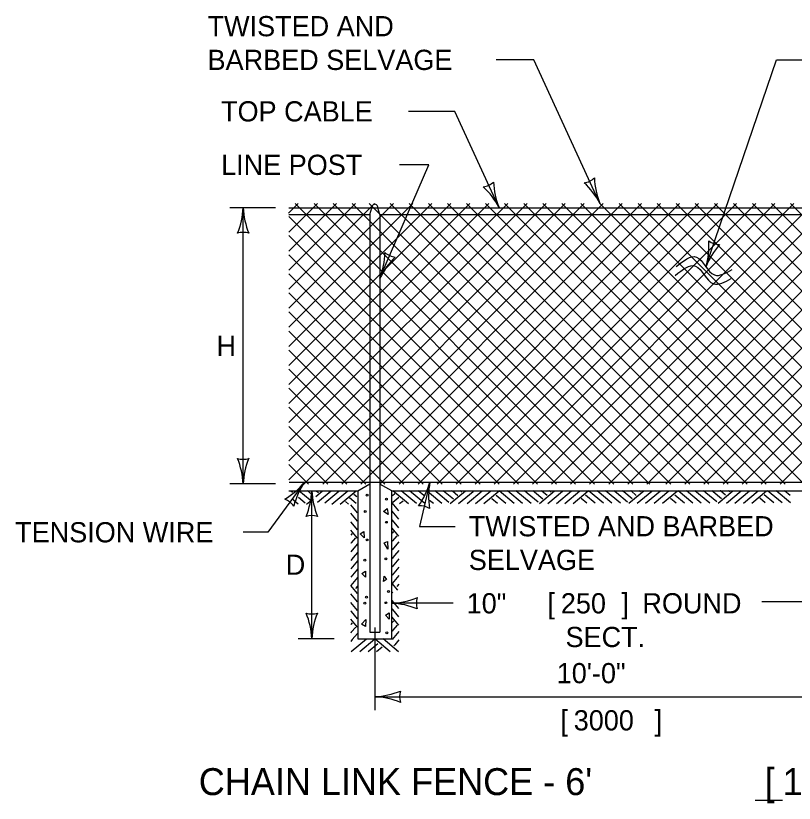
# Model space of a CAD drawing. Extents: x 49973.1 to 50021, y 49987.6 to 50015.4.
# Drawn here: x 49973.659 to 49975.97, y 50013.026 to 50015.363 of the extents above; entities that cross this region are included whole.
import ezdxf

# ---------------------------------------------------------------- set-up
doc = ezdxf.new("R2010")
doc.units = 0
for name, color, linetype in [('Level 1', 7, 'Continuous'), ('Level 2', 7, 'Continuous'), ('Level 3', 7, 'Continuous'), ('Level 6', 7, 'Continuous')]:
    doc.layers.add(name, color=color, linetype=linetype)

msp = doc.modelspace()

# ---------------------------------------------------------------- linework, layer by layer
at = {"layer": 'Level 1'}
for p, q in [((49974.4694, 50014.7766), (49974.4981, 50014.8053)), ((49974.4702, 50014.7208), (49974.5547, 50014.8053)), ((49974.4702, 50014.6642), (49974.6113, 50014.8053)), ((49974.4702, 50014.6076), (49974.6679, 50014.8053)), ((49974.4702, 50014.7932), (49977.3392, 50014.7932)), ((49974.4703, 50014.5513), (49974.7243, 50014.8053)), ((49974.4703, 50014.4947), (49974.7809, 50014.8053)), ((49974.4703, 50014.2683), (49975.0073, 50014.8053)), ((49974.4703, 50014.2119), (49975.0637, 50014.8053)), ((49974.4703, 50014.3815), (49974.8941, 50014.8053)), ((49974.4703, 50014.3249), (49974.9507, 50014.8053)), ((49974.4703, 50014.4381), (49974.8375, 50014.8053)), ((49974.4704, 50014.1554), (49975.1203, 50014.8053)), ((49974.4704, 50014.0422), (49975.2335, 50014.8053)), ((49974.4704, 50014.0988), (49975.1769, 50014.8053)), ((49974.4704, 50013.9856), (49975.2901, 50014.8053)), ((49974.4884, 50014.8053), (49975.321, 50013.9729)), ((49974.5143, 50013.9729), (49975.3467, 50014.8053)), ((49974.5452, 50014.8053), (49975.3776, 50013.9729)), ((49974.5709, 50013.9729), (49975.4033, 50014.8053)), ((49974.6016, 50014.8053), (49975.4342, 50013.9729)), ((49974.6273, 50013.9729), (49975.4597, 50014.8053)), ((49974.6582, 50014.8053), (49975.4908, 50013.9729)), ((49974.6839, 50013.9729), (49975.5163, 50014.8053)), ((49974.7087, 50014.8053), (49975.5416, 50013.9729)), ((49974.7102, 50014.7732), (49974.7165, 50014.7927)), ((49974.7402, 50014.7732), (49974.7342, 50014.793)), ((49974.7405, 50013.9729), (49975.5729, 50014.8053)), ((49974.7707, 50014.8053), (49975.6038, 50013.9729)), ((49974.7971, 50013.9729), (49975.6295, 50014.8053)), ((49974.8275, 50014.8053), (49975.6604, 50013.9729)), ((49974.8537, 50013.9729), (49975.6861, 50014.8053)), ((49974.8843, 50014.8053), (49975.717, 50013.9729)), ((49974.9103, 50013.9729), (49975.7427, 50014.8053)), ((49974.9407, 50014.8053), (49975.7736, 50013.9729)), ((49974.9667, 50013.9729), (49975.7991, 50014.8053)), ((49974.9976, 50014.8053), (49975.8302, 50013.9729)), ((49975.0233, 50013.9729), (49975.8557, 50014.8053)), ((49975.0537, 50014.8053), (49975.8866, 50013.9729)), ((49975.0799, 50013.9729), (49975.9123, 50014.8053)), ((49975.1101, 50014.8053), (49975.9432, 50013.9729)), ((49975.1365, 50013.9729), (49975.9689, 50014.8053)), ((49975.1672, 50014.8053), (49975.9998, 50013.9729)), ((49975.1931, 50013.9729), (49976.0255, 50014.8053)), ((49975.2235, 50014.8053), (49976.0564, 50013.9729)), ((49975.2497, 50013.9729), (49976.0821, 50014.8053)), ((49975.2804, 50014.8053), (49976.113, 50013.9729)), ((49975.3061, 50013.9729), (49976.1385, 50014.8053)), ((49975.337, 50014.8053), (49976.1696, 50013.9729)), ((49975.3627, 50013.9729), (49976.1951, 50014.8053)), ((49975.3935, 50014.8053), (49976.2262, 50013.9729)), ((49975.4193, 50013.9729), (49976.2517, 50014.8053)), ((49975.45, 50014.8053), (49976.2826, 50013.9729)), ((49975.4759, 50013.9729), (49976.3083, 50014.8053)), ((49975.5068, 50014.8053), (49976.3392, 50013.9729)), ((49975.5325, 50013.9729), (49976.3649, 50014.8053)), ((49975.5633, 50014.8053), (49976.3958, 50013.9729)), ((49975.5891, 50013.9729), (49976.4215, 50014.8053)), ((49975.6199, 50014.8053), (49976.4524, 50013.9729)), ((49975.6457, 50013.9729), (49976.4781, 50014.8053)), ((49975.6765, 50014.8053), (49976.509, 50013.9729)), ((49975.7021, 50013.9729), (49976.5345, 50014.8053)), ((49975.7331, 50014.8053), (49976.5656, 50013.9729)), ((49975.7587, 50013.9729), (49976.5911, 50014.8053)), ((49975.7895, 50014.8053), (49976.622, 50013.9729)), ((49975.8153, 50013.9729), (49976.6477, 50014.8053)), ((49975.8461, 50014.8053), (49976.6786, 50013.9729)), ((49975.8719, 50013.9729), (49976.7043, 50014.8053)), ((49975.9027, 50014.8053), (49976.7352, 50013.9729)), ((49975.9285, 50013.9729), (49976.7609, 50014.8053)), ((49975.9593, 50014.8053), (49976.7918, 50013.9729)), ((49974.4702, 50014.7732), (49974.7102, 50014.7732)), ((49974.7102, 50014.7732), (49974.7102, 50013.5332)), ((49974.7402, 50014.7732), (49974.7402, 50013.9729)), ((49974.7402, 50014.7732), (49976.1102, 50014.7732)), ((49974.4702, 50014.7668), (49975.2644, 50013.9729)), ((49974.4702, 50014.7102), (49975.2078, 50013.9729)), ((49974.4702, 50014.6534), (49975.1512, 50013.9729)), ((49974.4702, 50014.5966), (49975.0946, 50013.9729)), ((49974.4703, 50014.5401), (49975.038, 50013.9729)), ((49974.4703, 50014.4838), (49974.9814, 50013.9729)), ((49974.4703, 50014.4266), (49974.9248, 50013.9729)), ((49974.4703, 50014.3703), (49974.8682, 50013.9729)), ((49974.4703, 50014.3138), (49974.8116, 50013.9729)), ((49974.4703, 50014.2575), (49974.755, 50013.9729)), ((49974.4703, 50014.2008), (49974.6984, 50013.9729)), ((49974.4704, 50014.1442), (49974.6418, 50013.9729)), ((49974.4704, 50014.0876), (49974.5852, 50013.9729)), ((49974.4704, 50014.031), (49974.5286, 50013.9729)), ((49974.4705, 50013.9786), (49977.4631, 50013.9786)), ((49974.4704, 50013.9532), (49974.6752, 50013.9532)), ((49974.4811, 50013.9478), (49974.476, 50013.952)), ((49974.4998, 50013.9531), (49974.4997, 50013.9532)), ((49974.5335, 50013.925), (49974.5, 50013.9532)), ((49974.5291, 50013.9495), (49974.5252, 50013.9528)), ((49974.5503, 50013.9365), (49974.5687, 50013.9519)), ((49974.5525, 50013.9508), (49974.5504, 50013.9525)), ((49974.5575, 50013.9466), (49974.5525, 50013.9508)), ((49974.5552, 50013.9196), (49974.5953, 50013.9532)), ((49974.5769, 50013.917), (49974.6187, 50013.9519)), ((49974.5905, 50013.9492), (49974.5931, 50013.9514)), ((49974.5975, 50013.9131), (49974.6453, 50013.9532)), ((49974.6225, 50013.9131), (49974.6695, 50013.9526)), ((49974.6752, 50013.9532), (49974.7102, 50013.9732)), ((49974.6752, 50013.9532), (49974.6752, 50013.5141)), ((49974.7402, 50013.9729), (49974.7402, 50013.5332)), ((49974.7752, 50013.9531), (49974.7402, 50013.9725)), ((49974.7752, 50013.9532), (49976.0752, 50013.9532)), ((49974.7752, 50013.5141), (49974.7752, 50013.9531)), ((49974.8251, 50013.914), (49974.7791, 50013.9526)), ((49974.8489, 50013.915), (49974.8034, 50013.9532)), ((49974.8739, 50013.915), (49974.8285, 50013.9531)), ((49974.8702, 50013.9391), (49974.8534, 50013.9531)), ((49974.9125, 50013.9455), (49974.9033, 50013.9531)), ((49974.9341, 50013.9484), (49974.9284, 50013.9531)), ((49974.9489, 50013.915), (49974.9942, 50013.9531)), ((49974.9555, 50013.9514), (49974.9534, 50013.9531)), ((49974.9712, 50013.9383), (49974.9555, 50013.9514)), ((49974.9739, 50013.915), (49975.0169, 50013.9511)), ((49974.9789, 50013.9527), (49974.9784, 50013.9531)), ((49974.9839, 50013.9485), (49974.9789, 50013.9527)), ((49974.9989, 50013.915), (49975.0442, 50013.9531)), ((49975.0169, 50013.9511), (49975.0192, 50013.9531)), ((49975.0239, 50013.915), (49975.0692, 50013.9531)), ((49975.0489, 50013.915), (49975.0942, 50013.9531)), ((49975.139, 50013.9155), (49975.0942, 50013.9531)), ((49975.164, 50013.9155), (49975.119, 50013.9531)), ((49975.189, 50013.9155), (49975.144, 50013.9531)), ((49975.1776, 50013.946), (49975.169, 50013.9531)), ((49975.1992, 50013.9489), (49975.1941, 50013.9531)), ((49975.214, 50013.9155), (49975.2587, 50013.9531)), ((49975.2206, 50013.9519), (49975.2191, 50013.9531)), ((49975.2363, 50013.9388), (49975.2206, 50013.9519)), ((49975.239, 50013.9155), (49975.282, 50013.9516)), ((49975.249, 50013.949), (49975.244, 50013.9532)), ((49975.264, 50013.9155), (49975.3087, 50013.9531)), ((49975.282, 50013.9516), (49975.2837, 50013.9531)), ((49975.289, 50013.9155), (49975.3337, 50013.9531)), ((49975.314, 50013.9155), (49975.3587, 50013.9531)), ((49975.4041, 50013.916), (49975.3598, 50013.9531)), ((49975.4291, 50013.916), (49975.3847, 50013.9531)), ((49975.4541, 50013.916), (49975.4097, 50013.9531)), ((49975.4427, 50013.9465), (49975.4347, 50013.9531)), ((49975.4643, 50013.9494), (49975.4598, 50013.9531)), ((49975.4791, 50013.916), (49975.5232, 50013.9531)), ((49975.4857, 50013.9524), (49975.4848, 50013.9531)), ((49975.5014, 50013.9393), (49975.4857, 50013.9524)), ((49975.5041, 50013.916), (49975.5471, 50013.9521)), ((49975.5141, 50013.9495), (49975.5098, 50013.9531)), ((49975.5291, 50013.916), (49975.5732, 50013.9531)), ((49975.5471, 50013.9521), (49975.5482, 50013.9531)), ((49975.5541, 50013.916), (49975.5982, 50013.9531)), ((49975.5791, 50013.916), (49975.6232, 50013.9531)), ((49975.6692, 50013.9165), (49975.6255, 50013.9531)), ((49975.6942, 50013.9165), (49975.6504, 50013.9531)), ((49975.7192, 50013.9165), (49975.6754, 50013.9531)), ((49975.7078, 50013.947), (49975.7004, 50013.9531)), ((49975.7294, 50013.9499), (49975.7255, 50013.9531)), ((49975.7442, 50013.9165), (49975.7877, 50013.9531)), ((49975.7508, 50013.9529), (49975.7505, 50013.9531)), ((49975.7665, 50013.9398), (49975.7508, 50013.9529)), ((49975.7692, 50013.9165), (49975.8122, 50013.9526)), ((49975.7792, 50013.95), (49975.7755, 50013.9531)), ((49975.7942, 50013.9165), (49975.8377, 50013.9531)), ((49975.8122, 50013.9526), (49975.8127, 50013.9531)), ((49975.8192, 50013.9165), (49975.8627, 50013.9531)), ((49975.8442, 50013.9165), (49975.8877, 50013.9531)), ((49975.9343, 50013.917), (49975.8912, 50013.9531)), ((49975.9593, 50013.917), (49975.9161, 50013.9531)), ((49975.9585, 50013.9386), (49975.9411, 50013.9531)), ((49974.4975, 50013.9131), (49974.4787, 50013.9288)), ((49974.4811, 50013.9478), (49974.4811, 50013.9478)), ((49974.5185, 50013.9166), (49974.4986, 50013.9333)), ((49974.5402, 50013.9403), (49974.5291, 50013.9495)), ((49974.5876, 50013.9468), (49974.5905, 50013.9492)), ((49974.6702, 50013.915), (49974.6504, 50013.9317)), ((49974.6713, 50013.9351), (49974.6633, 50013.9418)), ((49974.7778, 50013.9393), (49974.7844, 50013.9448)), ((49974.779, 50013.9193), (49974.7969, 50013.9343)), ((49974.9239, 50013.915), (49974.8874, 50013.9456)), ((49974.9448, 50013.9184), (49974.9125, 50013.9455)), ((49974.9587, 50013.9278), (49974.9341, 50013.9484)), ((49975.089, 50013.9155), (49975.0727, 50013.9292)), ((49975.114, 50013.9155), (49975.0856, 50013.9393)), ((49975.2099, 50013.9189), (49975.1776, 50013.946)), ((49975.2238, 50013.9283), (49975.1992, 50013.9489)), ((49975.3541, 50013.916), (49975.3378, 50013.9297)), ((49975.3791, 50013.916), (49975.3507, 50013.9398)), ((49975.475, 50013.9194), (49975.4427, 50013.9465)), ((49975.4889, 50013.9288), (49975.4643, 50013.9494)), ((49975.6192, 50013.9165), (49975.6029, 50013.9302)), ((49975.6442, 50013.9165), (49975.6158, 50013.9403)), ((49975.7401, 50013.9199), (49975.7078, 50013.947)), ((49975.754, 50013.9293), (49975.7294, 50013.9499)), ((49975.8843, 50013.917), (49975.868, 50013.9307)), ((49975.9093, 50013.917), (49975.8809, 50013.9408)), ((49974.5225, 50013.9131), (49974.5372, 50013.9254)), ((49974.6475, 50013.9131), (49974.6382, 50013.9209)), ((49974.6736, 50013.8875), (49974.6537, 50013.9112)), ((49974.7965, 50013.8934), (49974.7766, 50013.9171)), ((49974.7989, 50013.915), (49974.8091, 50013.9235)), ((49974.8989, 50013.915), (49974.8875, 50013.9246)), ((49974.6736, 50013.8625), (49974.6537, 50013.8862)), ((49974.7965, 50013.8684), (49974.7766, 50013.8921)), ((49974.6552, 50013.8595), (49974.6537, 50013.8612)), ((49974.6736, 50013.8375), (49974.6552, 50013.8595)), ((49974.7781, 50013.8654), (49974.7766, 50013.8671)), ((49974.7965, 50013.8434), (49974.7781, 50013.8654)), ((49974.6736, 50013.8125), (49974.6537, 50013.8362)), ((49974.7965, 50013.8184), (49974.7766, 50013.8421)), ((49974.6578, 50013.8265), (49974.6536, 50013.8215)), ((49974.668, 50013.8138), (49974.6549, 50013.7981)), ((49974.7807, 50013.8324), (49974.7765, 50013.8274)), ((49974.7909, 50013.8197), (49974.7778, 50013.804)), ((49974.6549, 50013.7981), (49974.6537, 50013.7966)), ((49974.6736, 50013.7954), (49974.6579, 50013.7767)), ((49974.7778, 50013.804), (49974.7766, 50013.8025)), ((49974.7965, 50013.8013), (49974.7808, 50013.7826)), ((49974.6579, 50013.7767), (49974.6537, 50013.7716)), ((49974.6736, 50013.7703), (49974.6608, 50013.7551)), ((49974.7808, 50013.7826), (49974.7766, 50013.7775)), ((49974.7965, 50013.7762), (49974.7837, 50013.761)), ((49974.6608, 50013.7551), (49974.6537, 50013.7465)), ((49974.6736, 50013.7453), (49974.6537, 50013.7215)), ((49974.7837, 50013.761), (49974.7766, 50013.7524)), ((49974.7965, 50013.7512), (49974.7766, 50013.7274)), ((49974.6736, 50013.7203), (49974.6537, 50013.6965)), ((49974.7965, 50013.7262), (49974.7766, 50013.7024)), ((49974.6736, 50013.6954), (49974.6537, 50013.6717)), ((49974.7965, 50013.7013), (49974.7766, 50013.6776)), ((49974.6736, 50013.648), (49974.6537, 50013.6717)), ((49974.6736, 50013.6703), (49974.6675, 50013.6631)), ((49974.7934, 50013.6576), (49974.7766, 50013.6776)), ((49974.7965, 50013.6762), (49974.7904, 50013.669)), ((49974.6736, 50013.623), (49974.6537, 50013.6467)), ((49974.779, 50013.6497), (49974.7766, 50013.6526)), ((49974.7965, 50013.6039), (49974.7766, 50013.6276)), ((49974.6736, 50013.598), (49974.6537, 50013.6217)), ((49974.7786, 50013.6003), (49974.7766, 50013.6026)), ((49974.7965, 50013.5789), (49974.7786, 50013.6003)), ((49974.6557, 50013.5944), (49974.6537, 50013.5967)), ((49974.6736, 50013.573), (49974.6557, 50013.5944)), ((49974.7965, 50013.5539), (49974.7766, 50013.5776)), ((49974.6736, 50013.548), (49974.6537, 50013.5717)), ((49974.6541, 50013.5564), (49974.6537, 50013.5559)), ((49974.6583, 50013.5614), (49974.6541, 50013.5564)), ((49974.777, 50013.5623), (49974.7766, 50013.5618)), ((49974.7812, 50013.5673), (49974.777, 50013.5623)), ((49974.7914, 50013.5546), (49974.7783, 50013.5389)), ((49974.6554, 50013.533), (49974.6537, 50013.5309)), ((49974.6685, 50013.5487), (49974.6554, 50013.533)), ((49974.6736, 50013.5297), (49974.6584, 50013.5116)), ((49974.7102, 50013.5332), (49974.7402, 50013.5332)), ((49974.7783, 50013.5389), (49974.7766, 50013.5368)), ((49974.7965, 50013.5356), (49974.7813, 50013.5175)), ((49974.6584, 50013.5116), (49974.6537, 50013.5059)), ((49974.6553, 50013.4757), (49974.7003, 50013.5133)), ((49974.6752, 50013.5141), (49974.7752, 50013.5141)), ((49974.6803, 50013.4757), (49974.7251, 50013.5133)), ((49974.7704, 50013.4752), (49974.7251, 50013.5133)), ((49974.7954, 50013.4752), (49974.7501, 50013.5133)), ((49974.7813, 50013.5175), (49974.7766, 50013.5118)), ((49974.7965, 50013.5105), (49974.7842, 50013.4959)), ((49974.7053, 50013.4757), (49974.7337, 50013.4995)), ((49974.7303, 50013.4757), (49974.7466, 50013.4894)), ((49974.7842, 50013.4959), (49974.7818, 50013.493))]:
    msp.add_line(p, q, dxfattribs=at)
for points in [[(49974.7512, 50013.8919), (49974.7622, 50013.9001), (49974.7643, 50013.8822)], [(49974.6817, 50013.8249), (49974.6927, 50013.8318), (49974.6934, 50013.8133)], [(49974.7533, 50013.7986), (49974.7629, 50013.8021), (49974.7636, 50013.7794)], [(49974.6862, 50013.7078), (49974.6972, 50013.7147), (49974.6979, 50013.6962)], [(49974.7507, 50013.6839), (49974.7528, 50013.6996), (49974.7596, 50013.6894)], [(49974.7564, 50013.584), (49974.7674, 50013.5909), (49974.7681, 50013.5724)], [(49974.686, 50013.5568), (49974.6984, 50013.5712), (49974.697, 50013.55)]]:
    msp.add_lwpolyline(points, close=True, dxfattribs=at)
for centre in [(49974.702, 50013.9399), (49974.7594, 50013.9284), (49974.6969, 50013.8914), (49974.7594, 50013.8595), (49974.702, 50013.8071), (49974.6956, 50013.7471), (49974.7582, 50013.751), (49974.7658, 50013.6539), (49974.7007, 50013.6373), (49974.7582, 50013.6208), (49974.6956, 50013.6195), (49974.7607, 50013.5314)]:
    msp.add_circle(centre, 0.00279, dxfattribs=at)
msp.add_arc((49974.7254, 50014.7942), 0.00895, 352.3754, 189.572, dxfattribs=at)
at = {"layer": 'Level 2'}
msp.add_line((49975.9357, 50013.0338), (49975.8538, 50013.0338), dxfattribs=at)
at = {"layer": 'Level 3'}
for p, q in [((49975.1975, 50015.2319), (49975.0856, 50015.2319)), ((49975.3935, 50014.8053), (49975.1975, 50015.2319)), ((49975.7082, 50014.6172), (49975.9173, 50015.2319)), ((49975.9173, 50015.2319), (49975.9994, 50015.2319)), ((49974.9627, 50015.0791), (49974.8256, 50015.0791)), ((49975.0941, 50014.7932), (49974.9627, 50015.0791)), ((49974.7402, 50014.5836), (49974.8859, 50014.9204)), ((49974.8859, 50014.9204), (49974.7981, 50014.9204)), ((49974.4302, 50014.7932), (49974.2943, 50014.7932)), ((49974.3343, 50013.9732), (49974.3343, 50014.7932)), ((49974.5168, 50013.9786), (49974.4079, 50013.8299)), ((49974.8885, 50013.9786), (49974.8579, 50013.8472)), ((49974.4305, 50013.9732), (49974.2943, 50013.9732)), ((49974.5381, 50013.5141), (49974.5381, 50013.9532)), ((49974.8579, 50013.8472), (49974.9641, 50013.8472)), ((49974.4079, 50013.8299), (49974.3343, 50013.8299)), ((49975.8744, 50013.6247), (49976.0752, 50013.6247)), ((49974.9578, 50013.6191), (49974.7752, 50013.6191)), ((49974.7252, 50013.5471), (49974.7252, 50013.3018)), ((49974.6045, 50013.5141), (49974.4981, 50013.5141)), ((49974.7252, 50013.3418), (49976.1261, 50013.3418))]:
    msp.add_line(p, q, dxfattribs=at)
for centre, radius, start, end in [((49975.0405, 50014.9097), 0.0548, 276.8211, 312.5434), ((49975.2997, 50014.8777), 0.2223, 182.1383, 202.3218), ((49975.34, 50014.9218), 0.0548, 276.8211, 312.5434), ((49975.1869, 50014.6977), 0.233, 27.5096, 46.7594), ((49975.5992, 50014.8898), 0.2223, 182.1383, 202.3218), ((49974.8874, 50014.6856), 0.233, 27.5096, 46.7594), ((49974.1122, 50014.8024), 0.2223, 337.456, 357.6395), ((49974.5671, 50014.8047), 0.233, 182.8273, 202.0772), ((49974.3343, 50014.665), 0.0548, 72.1388, 107.8612), ((49975.484, 50014.6805), 0.233, 344.2336, 3.4835), ((49975.9158, 50014.5376), 0.2223, 138.8623, 159.0459), ((49975.7491, 50014.7387), 0.0548, 233.5452, 269.2675), ((49974.5221, 50014.6655), 0.233, 339.4345, 358.6844), ((49974.7911, 50014.7013), 0.0548, 228.746, 264.4684), ((49974.9405, 50014.487), 0.2223, 134.0632, 154.2467), ((49974.3343, 50014.1014), 0.0548, 252.1388, 287.8612), ((49974.1016, 50013.9617), 0.233, 2.8273, 22.0772), ((49974.5565, 50013.9641), 0.2223, 157.456, 177.6395), ((49974.3448, 50014.1195), 0.2223, 300.5072, 320.6907), ((49974.7097, 50013.8479), 0.233, 145.8785, 165.1283), ((49974.6742, 50014.0379), 0.2223, 324.3468, 344.5303), ((49975.1178, 50013.937), 0.233, 169.7181, 188.968), ((49974.316, 50013.9624), 0.2223, 337.456, 357.6395), ((49974.7709, 50013.9647), 0.233, 182.8273, 202.0772), ((49974.4398, 50013.8762), 0.0548, 35.19, 70.9123), ((49974.8594, 50013.8538), 0.0548, 59.0296, 94.752), ((49974.5381, 50013.825), 0.0548, 72.1388, 107.8612), ((49974.7638, 50013.8518), 0.233, 272.8273, 292.0772), ((49974.9035, 50013.6191), 0.0548, 162.1388, 197.8612), ((49974.7661, 50013.397), 0.2223, 67.456, 87.6395), ((49974.5381, 50013.6423), 0.0548, 252.1388, 287.8612), ((49974.3054, 50013.5026), 0.233, 2.8273, 22.0772), ((49974.7603, 50013.505), 0.2223, 157.456, 177.6395), ((49974.7138, 50013.5745), 0.233, 272.8273, 292.0772), ((49974.8535, 50013.3418), 0.0548, 162.1388, 197.8612), ((49974.7161, 50013.1197), 0.2223, 67.456, 87.6395)]:
    msp.add_arc(centre, radius, start, end, dxfattribs=at)
at = {"layer": 'Level 6'}
for points in [[(49975.6199, 50014.6186), (49975.6801, 50014.6465), (49975.7331, 50014.5937), (49975.786, 50014.6098)], [(49975.617, 50014.5922), (49975.6772, 50014.6201), (49975.7302, 50014.5673), (49975.7831, 50014.5834)]]:
    msp.add_spline(points, degree=3, dxfattribs=at)

# ---------------------------------------------------------------- texts
at = {"layer": 'Level 2'}
for s, height, p in [('TWISTED AND', 0.06, (49974.2287, 50015.3019)), ('BARBED SELVAGE', 0.06, (49974.2287, 50015.2019)), ('TOP CABLE', 0.06, (49974.2687, 50015.0491)), ('LINE POST', 0.06, (49974.2689, 50014.8904)), ('H', 0.06, (49974.2551, 50014.3532)), ('TENSION WIRE', 0.06, (49973.6575, 50013.7999)), ('TWISTED AND BARBED', 0.06, (49975.0041, 50013.8178)), ('D', 0.06, (49974.4608, 50013.7036)), ('SELVAGE', 0.06, (49975.0041, 50013.7178)), ('10" ', 0.06, (49974.9978, 50013.5891)), ('[', 0.06, (49975.2378, 50013.5891)), ('250', 0.06, (49975.2774, 50013.5891)), (']', 0.06, (49975.4574, 50013.5891)), (' ROUND', 0.06, (49975.4971, 50013.5891)), ('SECT.', 0.06, (49975.2913, 50013.4891)), ('10\'-0"', 0.06, (49975.2651, 50013.3818)), ('[', 0.06, (49975.2759, 50013.2418)), ('3000', 0.06, (49975.3156, 50013.2418)), (']', 0.06, (49975.5556, 50013.2418)), ('[', 0.08, (49975.8826, 50013.0498)), ("CHAIN LINK FENCE - 6' ", 0.08, (49974.2026, 50013.0498)), ('1.8 m', 0.08, (49975.9355, 50013.0498))]:
    msp.add_text(s, height=height, dxfattribs=at).set_placement(p)

doc.saveas('drawing.dxf')
